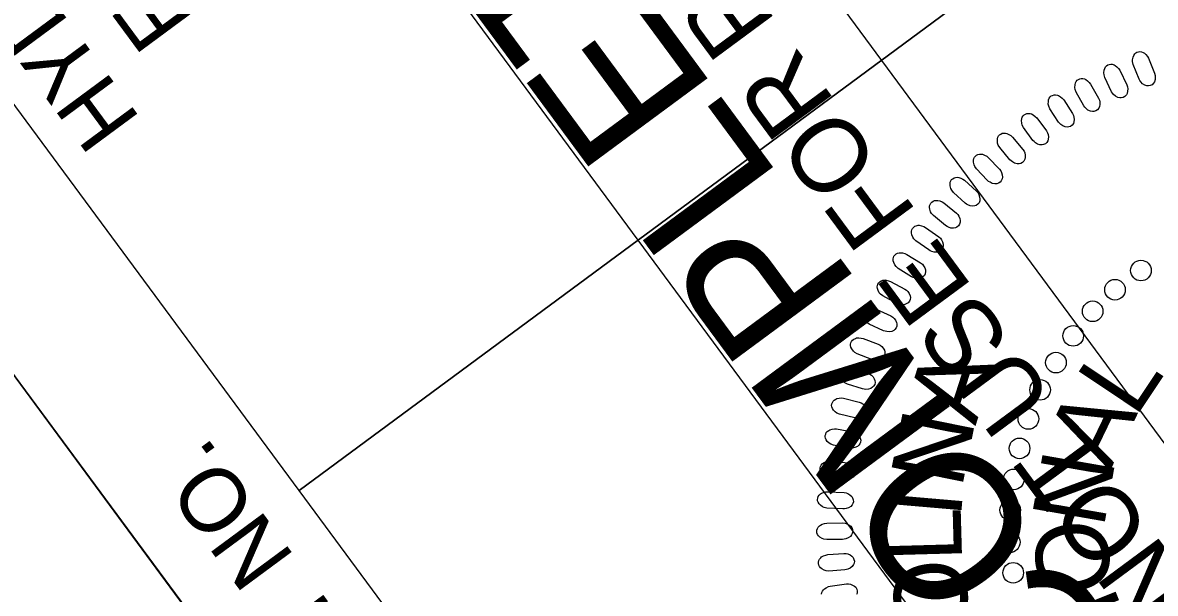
# Model space of a CAD drawing. Extents: x 474314 to 476195, y 501901 to 503905.
# Drawn here: x 474410.1 to 474498.1, y 503188.4 to 503232.7 of the extents above; entities that cross this region are included whole.
import ezdxf

# ---------------------------------------------------------------- set-up
doc = ezdxf.new("R2010")
doc.units = 0
for name, color, linetype in [('Sheet PE Seal Cell', 7, 'Continuous'), ('Sheet Plan CELL', 7, 'Continuous'), ('Sheet Sticker Exception Certification CELL', 7, 'Continuous'), ('Sheet Sticker Incomplete CELL', 7, 'Continuous')]:
    doc.layers.add(name, color=color, linetype=linetype)

msp = doc.modelspace()

# ---------------------------------------------------------------- linework, layer by layer
at = {"layer": 'Sheet PE Seal Cell'}
for points in [[(474496.879, 503228.322), (474496.419, 503229.459), (474496.371, 503229.676), (474496.367, 503229.825), (474496.407, 503230.025), (474496.456, 503230.162), (474496.531, 503230.279), (474496.612, 503230.354), (474496.709, 503230.415), (474496.82, 503230.439), (474496.943, 503230.456), (474497.062, 503230.44), (474497.196, 503230.386), (474497.282, 503230.335), (474497.4, 503230.221), (474497.523, 503230.078), (474497.604, 503229.938), (474498.082, 503228.776), (474498.124, 503228.61), (474498.135, 503228.464), (474498.112, 503228.283), (474498.06, 503228.111), (474498.001, 503228.001), (474497.877, 503227.886), (474497.746, 503227.812), (474497.593, 503227.793), (474497.477, 503227.8), (474497.321, 503227.844), (474497.147, 503227.957), (474497.017, 503228.098), (474496.942, 503228.207)], [(474494.743, 503227.343), (474494.213, 503228.449), (474494.152, 503228.662), (474494.138, 503228.811), (474494.166, 503229.013), (474494.206, 503229.154), (474494.273, 503229.274), (474494.35, 503229.355), (474494.443, 503229.422), (474494.552, 503229.452), (474494.673, 503229.477), (474494.793, 503229.468), (474494.931, 503229.423), (474495.019, 503229.377), (474495.144, 503229.272), (474495.276, 503229.136), (474495.365, 503229.002), (474495.915, 503227.872), (474495.969, 503227.709), (474495.988, 503227.564), (474495.976, 503227.381), (474495.936, 503227.207), (474495.883, 503227.093), (474495.767, 503226.971), (474495.641, 503226.888), (474495.489, 503226.86), (474495.373, 503226.859), (474495.215, 503226.894), (474495.034, 503226.996), (474494.895, 503227.129), (474494.813, 503227.233)], [(474492.587, 503226.243), (474491.988, 503227.315), (474491.914, 503227.524), (474491.891, 503227.671), (474491.906, 503227.875), (474491.937, 503228.018), (474491.996, 503228.142), (474492.068, 503228.228), (474492.157, 503228.3), (474492.264, 503228.337), (474492.383, 503228.369), (474492.503, 503228.368), (474492.643, 503228.332), (474492.734, 503228.292), (474492.866, 503228.194), (474493.006, 503228.067), (474493.104, 503227.939), (474493.724, 503226.845), (474493.787, 503226.686), (474493.816, 503226.543), (474493.815, 503226.36), (474493.786, 503226.183), (474493.74, 503226.066), (474493.632, 503225.937), (474493.512, 503225.847), (474493.361, 503225.809), (474493.246, 503225.801), (474493.086, 503225.826), (474492.9, 503225.916), (474492.752, 503226.039), (474492.664, 503226.138)], [(474490.606, 503224.988), (474489.941, 503226.019), (474489.854, 503226.223), (474489.822, 503226.369), (474489.824, 503226.573), (474489.846, 503226.717), (474489.897, 503226.845), (474489.963, 503226.935), (474490.048, 503227.013), (474490.152, 503227.056), (474490.269, 503227.096), (474490.389, 503227.103), (474490.531, 503227.075), (474490.624, 503227.041), (474490.763, 503226.952), (474490.91, 503226.833), (474491.016, 503226.711), (474491.703, 503225.659), (474491.776, 503225.505), (474491.813, 503225.363), (474491.825, 503225.181), (474491.806, 503225.003), (474491.768, 503224.882), (474491.669, 503224.747), (474491.553, 503224.649), (474491.406, 503224.602), (474491.291, 503224.587), (474491.131, 503224.602), (474490.938, 503224.68), (474490.784, 503224.794), (474490.69, 503224.887)], [(474488.623, 503223.564), (474487.895, 503224.552), (474487.795, 503224.75), (474487.754, 503224.894), (474487.743, 503225.097), (474487.756, 503225.243), (474487.799, 503225.373), (474487.86, 503225.467), (474487.939, 503225.55), (474488.04, 503225.601), (474488.154, 503225.648), (474488.274, 503225.662), (474488.417, 503225.644), (474488.513, 503225.615), (474488.656, 503225.534), (474488.811, 503225.426), (474488.923, 503225.311), (474489.676, 503224.304), (474489.758, 503224.155), (474489.805, 503224.015), (474489.827, 503223.833), (474489.82, 503223.655), (474489.79, 503223.533), (474489.699, 503223.391), (474489.59, 503223.287), (474489.446, 503223.23), (474489.333, 503223.208), (474489.171, 503223.212), (474488.974, 503223.278), (474488.813, 503223.383), (474488.712, 503223.469)], [(474486.837, 503222.06), (474486.049, 503223), (474485.937, 503223.192), (474485.886, 503223.332), (474485.863, 503223.534), (474485.867, 503223.68), (474485.902, 503223.814), (474485.956, 503223.911), (474486.029, 503223.999), (474486.128, 503224.056), (474486.238, 503224.11), (474486.357, 503224.131), (474486.501, 503224.122), (474486.598, 503224.099), (474486.746, 503224.029), (474486.908, 503223.929), (474487.027, 503223.822), (474487.841, 503222.864), (474487.933, 503222.72), (474487.988, 503222.584), (474488.022, 503222.404), (474488.026, 503222.225), (474488.003, 503222.102), (474487.922, 503221.955), (474487.82, 503221.843), (474487.68, 503221.778), (474487.567, 503221.749), (474487.406, 503221.743), (474487.206, 503221.796), (474487.038, 503221.89), (474486.932, 503221.97)], [(474485.08, 503220.459), (474484.234, 503221.348), (474484.109, 503221.532), (474484.05, 503221.669), (474484.015, 503221.869), (474484.009, 503222.016), (474484.035, 503222.151), (474484.083, 503222.252), (474484.151, 503222.343), (474484.246, 503222.406), (474484.353, 503222.467), (474484.47, 503222.497), (474484.615, 503222.496), (474484.713, 503222.48), (474484.865, 503222.418), (474485.033, 503222.329), (474485.159, 503222.229), (474486.031, 503221.325), (474486.132, 503221.186), (474486.196, 503221.054), (474486.241, 503220.877), (474486.256, 503220.699), (474486.24, 503220.574), (474486.169, 503220.422), (474486.073, 503220.304), (474485.938, 503220.231), (474485.828, 503220.195), (474485.667, 503220.179), (474485.464, 503220.219), (474485.291, 503220.303), (474485.18, 503220.376)], [(474483.354, 503218.69), (474482.454, 503219.523), (474482.318, 503219.7), (474482.251, 503219.833), (474482.203, 503220.03), (474482.188, 503220.176), (474482.205, 503220.313), (474482.247, 503220.416), (474482.309, 503220.512), (474482.4, 503220.581), (474482.504, 503220.648), (474482.618, 503220.684), (474482.762, 503220.694), (474482.861, 503220.684), (474483.017, 503220.631), (474483.189, 503220.553), (474483.322, 503220.462), (474484.249, 503219.613), (474484.359, 503219.482), (474484.43, 503219.354), (474484.486, 503219.18), (474484.513, 503219.003), (474484.506, 503218.878), (474484.443, 503218.721), (474484.356, 503218.598), (474484.225, 503218.516), (474484.118, 503218.473), (474483.958, 503218.447), (474483.753, 503218.475), (474483.574, 503218.547), (474483.46, 503218.613)], [(474481.843, 503216.941), (474480.893, 503217.716), (474480.747, 503217.883), (474480.671, 503218.012), (474480.61, 503218.206), (474480.586, 503218.351), (474480.596, 503218.488), (474480.631, 503218.594), (474480.686, 503218.694), (474480.772, 503218.768), (474480.872, 503218.842), (474480.983, 503218.885), (474481.127, 503218.903), (474481.227, 503218.9), (474481.385, 503218.857), (474481.562, 503218.79), (474481.7, 503218.707), (474482.679, 503217.919), (474482.796, 503217.794), (474482.876, 503217.671), (474482.943, 503217.501), (474482.981, 503217.326), (474482.981, 503217.2), (474482.928, 503217.041), (474482.849, 503216.912), (474482.724, 503216.822), (474482.619, 503216.772), (474482.462, 503216.736), (474482.255, 503216.751), (474482.073, 503216.812), (474481.953, 503216.871)], [(474480.538, 503215.051), (474479.54, 503215.765), (474479.383, 503215.923), (474479.3, 503216.046), (474479.228, 503216.236), (474479.194, 503216.379), (474479.195, 503216.517), (474479.223, 503216.625), (474479.273, 503216.728), (474479.354, 503216.807), (474479.448, 503216.887), (474479.557, 503216.937), (474479.7, 503216.964), (474479.799, 503216.967), (474479.961, 503216.935), (474480.141, 503216.879), (474480.284, 503216.804), (474481.311, 503216.079), (474481.435, 503215.963), (474481.522, 503215.844), (474481.6, 503215.679), (474481.649, 503215.507), (474481.657, 503215.381), (474481.615, 503215.218), (474481.543, 503215.085), (474481.424, 503214.987), (474481.323, 503214.931), (474481.167, 503214.885), (474480.96, 503214.887), (474480.775, 503214.936), (474480.652, 503214.987)], [(474479.196, 503212.973), (474478.155, 503213.622), (474477.989, 503213.77), (474477.898, 503213.888), (474477.813, 503214.073), (474477.772, 503214.214), (474477.764, 503214.351), (474477.785, 503214.461), (474477.828, 503214.567), (474477.905, 503214.651), (474477.993, 503214.737), (474478.098, 503214.794), (474478.239, 503214.83), (474478.338, 503214.839), (474478.501, 503214.817), (474478.685, 503214.772), (474478.832, 503214.707), (474479.902, 503214.048), (474480.034, 503213.939), (474480.129, 503213.827), (474480.216, 503213.666), (474480.276, 503213.498), (474480.292, 503213.372), (474480.259, 503213.207), (474480.197, 503213.07), (474480.084, 503212.965), (474479.986, 503212.902), (474479.834, 503212.847), (474479.627, 503212.836), (474479.439, 503212.873), (474479.314, 503212.917)], [(474478.039, 503210.901), (474476.96, 503211.484), (474476.785, 503211.621), (474476.686, 503211.733), (474476.591, 503211.913), (474476.54, 503212.05), (474476.523, 503212.187), (474476.538, 503212.298), (474476.574, 503212.406), (474476.645, 503212.495), (474476.728, 503212.586), (474476.83, 503212.65), (474476.968, 503212.695), (474477.066, 503212.709), (474477.23, 503212.698), (474477.416, 503212.664), (474477.567, 503212.608), (474478.677, 503212.018), (474478.815, 503211.917), (474478.917, 503211.812), (474479.014, 503211.657), (474479.084, 503211.492), (474479.108, 503211.369), (474479.086, 503211.202), (474479.032, 503211.061), (474478.926, 503210.949), (474478.832, 503210.88), (474478.684, 503210.815), (474478.478, 503210.791), (474478.288, 503210.817), (474478.16, 503210.853)], [(474477.021, 503208.773), (474475.907, 503209.287), (474475.724, 503209.413), (474475.619, 503209.518), (474475.512, 503209.691), (474475.453, 503209.825), (474475.428, 503209.961), (474475.436, 503210.073), (474475.464, 503210.183), (474475.53, 503210.276), (474475.607, 503210.372), (474475.704, 503210.442), (474475.839, 503210.496), (474475.936, 503210.516), (474476.101, 503210.515), (474476.289, 503210.494), (474476.443, 503210.447), (474477.587, 503209.928), (474477.732, 503209.836), (474477.84, 503209.737), (474477.947, 503209.588), (474478.026, 503209.429), (474478.059, 503209.307), (474478.047, 503209.139), (474478.003, 503208.995), (474477.904, 503208.876), (474477.815, 503208.802), (474477.671, 503208.728), (474477.467, 503208.691), (474477.275, 503208.705), (474477.145, 503208.732)], [(474476.122, 503206.541), (474474.978, 503206.984), (474474.786, 503207.098), (474474.675, 503207.197), (474474.557, 503207.362), (474474.49, 503207.493), (474474.456, 503207.626), (474474.457, 503207.739), (474474.479, 503207.85), (474474.538, 503207.947), (474474.609, 503208.048), (474474.702, 503208.124), (474474.834, 503208.186), (474474.929, 503208.213), (474475.094, 503208.221), (474475.282, 503208.212), (474475.439, 503208.176), (474476.614, 503207.729), (474476.763, 503207.647), (474476.877, 503207.554), (474476.994, 503207.413), (474477.084, 503207.258), (474477.123, 503207.138), (474477.122, 503206.971), (474477.086, 503206.824), (474476.996, 503206.699), (474476.911, 503206.62), (474476.772, 503206.537), (474476.571, 503206.486), (474476.379, 503206.489), (474476.247, 503206.508)], [(474475.388, 503204.258), (474474.219, 503204.629), (474474.021, 503204.73), (474473.903, 503204.822), (474473.775, 503204.98), (474473.701, 503205.106), (474473.658, 503205.237), (474473.652, 503205.349), (474473.666, 503205.462), (474473.72, 503205.563), (474473.784, 503205.667), (474473.872, 503205.749), (474473.999, 503205.819), (474474.094, 503205.852), (474474.257, 503205.871), (474474.446, 503205.874), (474474.604, 503205.847), (474475.805, 503205.475), (474475.959, 503205.402), (474476.08, 503205.317), (474476.204, 503205.184), (474476.303, 503205.034), (474476.35, 503204.918), (474476.36, 503204.75), (474476.334, 503204.601), (474476.251, 503204.471), (474476.172, 503204.387), (474476.038, 503204.295), (474475.84, 503204.232), (474475.649, 503204.222), (474475.516, 503204.233)], [(474474.79, 503202.001), (474473.599, 503202.297), (474473.395, 503202.386), (474473.272, 503202.471), (474473.135, 503202.62), (474473.052, 503202.741), (474473.002, 503202.869), (474472.988, 503202.98), (474472.996, 503203.094), (474473.042, 503203.198), (474473.1, 503203.307), (474473.184, 503203.394), (474473.306, 503203.472), (474473.398, 503203.51), (474473.559, 503203.539), (474473.747, 503203.554), (474473.908, 503203.537), (474475.129, 503203.241), (474475.288, 503203.178), (474475.413, 503203.101), (474475.546, 503202.976), (474475.655, 503202.833), (474475.709, 503202.719), (474475.729, 503202.553), (474475.712, 503202.403), (474475.637, 503202.268), (474475.564, 503202.178), (474475.436, 503202.079), (474475.243, 503202.004), (474475.052, 503201.982), (474474.919, 503201.984)], [(474474.342, 503199.667), (474473.136, 503199.887), (474472.927, 503199.964), (474472.799, 503200.04), (474472.652, 503200.181), (474472.562, 503200.296), (474472.504, 503200.421), (474472.483, 503200.531), (474472.483, 503200.645), (474472.524, 503200.752), (474472.574, 503200.864), (474472.652, 503200.956), (474472.769, 503201.041), (474472.859, 503201.085), (474473.018, 503201.125), (474473.205, 503201.151), (474473.366, 503201.145), (474474.603, 503200.925), (474474.766, 503200.873), (474474.895, 503200.804), (474475.036, 503200.687), (474475.153, 503200.552), (474475.215, 503200.441), (474475.245, 503200.276), (474475.238, 503200.125), (474475.172, 503199.986), (474475.104, 503199.892), (474474.983, 503199.785), (474474.794, 503199.698), (474474.605, 503199.664), (474474.472, 503199.658)], [(474474.017, 503197.257), (474472.798, 503197.402), (474472.585, 503197.465), (474472.452, 503197.533), (474472.297, 503197.665), (474472.199, 503197.774), (474472.134, 503197.895), (474472.106, 503198.003), (474472.1, 503198.117), (474472.133, 503198.226), (474472.177, 503198.341), (474472.248, 503198.438), (474472.36, 503198.53), (474472.446, 503198.581), (474472.603, 503198.629), (474472.788, 503198.668), (474472.949, 503198.671), (474474.198, 503198.53), (474474.363, 503198.488), (474474.497, 503198.427), (474474.644, 503198.319), (474474.77, 503198.192), (474474.838, 503198.085), (474474.879, 503197.922), (474474.881, 503197.772), (474474.823, 503197.628), (474474.762, 503197.53), (474474.648, 503197.416), (474474.465, 503197.317), (474474.279, 503197.271), (474474.147, 503197.257)], [(474473.851, 503194.933), (474472.626, 503195.001), (474472.409, 503195.05), (474472.273, 503195.11), (474472.109, 503195.231), (474472.005, 503195.334), (474471.932, 503195.451), (474471.898, 503195.557), (474471.885, 503195.671), (474471.91, 503195.781), (474471.947, 503195.899), (474472.012, 503196), (474472.118, 503196.099), (474472.201, 503196.155), (474472.354, 503196.213), (474472.536, 503196.263), (474472.697, 503196.277), (474473.952, 503196.215), (474474.12, 503196.183), (474474.257, 503196.13), (474474.411, 503196.032), (474474.545, 503195.912), (474474.619, 503195.811), (474474.67, 503195.651), (474474.681, 503195.5), (474474.634, 503195.353), (474474.578, 503195.252), (474474.471, 503195.131), (474474.296, 503195.021), (474474.112, 503194.963), (474473.981, 503194.941)], [(474473.837, 503192.567), (474472.611, 503192.558), (474472.391, 503192.594), (474472.251, 503192.645), (474472.081, 503192.756), (474471.97, 503192.852), (474471.889, 503192.963), (474471.849, 503193.069), (474471.828, 503193.181), (474471.847, 503193.292), (474471.876, 503193.412), (474471.935, 503193.517), (474472.034, 503193.623), (474472.113, 503193.684), (474472.263, 503193.752), (474472.441, 503193.813), (474472.601, 503193.836), (474473.858, 503193.853), (474474.027, 503193.832), (474474.167, 503193.788), (474474.327, 503193.7), (474474.468, 503193.589), (474474.549, 503193.492), (474474.609, 503193.336), (474474.63, 503193.186), (474474.592, 503193.036), (474474.542, 503192.931), (474474.444, 503192.803), (474474.275, 503192.683), (474474.096, 503192.614), (474473.967, 503192.583)], [(474474.001, 503190.202), (474472.778, 503190.116), (474472.556, 503190.138), (474472.413, 503190.18), (474472.236, 503190.28), (474472.119, 503190.369), (474472.032, 503190.476), (474471.986, 503190.577), (474471.958, 503190.688), (474471.969, 503190.801), (474471.992, 503190.922), (474472.043, 503191.031), (474472.136, 503191.143), (474472.211, 503191.208), (474472.356, 503191.286), (474472.53, 503191.358), (474472.688, 503191.391), (474473.941, 503191.487), (474474.111, 503191.476), (474474.254, 503191.441), (474474.419, 503191.363), (474474.566, 503191.262), (474474.653, 503191.17), (474474.724, 503191.018), (474474.754, 503190.87), (474474.725, 503190.718), (474474.682, 503190.61), (474474.592, 503190.476), (474474.431, 503190.345), (474474.257, 503190.265), (474474.129, 503190.227)]]:
    msp.add_lwpolyline(points, close=True, dxfattribs=at)
msp.add_lwpolyline([(474472.206, 503188.313), (474472.219, 503188.435), (474472.265, 503188.547), (474472.349, 503188.664), (474472.421, 503188.734), (474472.56, 503188.821), (474472.73, 503188.903), (474472.885, 503188.947), (474474.13, 503189.121), (474474.301, 503189.121), (474474.445, 503189.096), (474474.615, 503189.028), (474474.769, 503188.935), (474474.86, 503188.85), (474474.941, 503188.702), (474474.98, 503188.556), (474474.961, 503188.403), (474474.925, 503188.292)], dxfattribs=at)
for centre in [(474497.02, 503213.452), (474495.001, 503211.962), (474493.267, 503210.286), (474491.754, 503208.378), (474490.415, 503206.301), (474489.183, 503204.183), (474488.273, 503201.928), (474487.585, 503199.639), (474487.136, 503197.229), (474486.862, 503194.85), (474486.826, 503192.349), (474487.094, 503189.974)]:
    msp.add_circle(centre, 0.801, dxfattribs=at)
at = {"layer": 'Sheet Plan CELL'}
for p, q in [((474481, 503108.466), (474362.144, 503269.364)), ((474481, 503108.466), (474362.144, 503269.364)), ((474431.609, 503196.366), (474522.068, 503263.187))]:
    msp.add_line(p, q, dxfattribs=at)
for points in [[(474431.609, 503196.366), (474372.199, 503276.79), (474462.698, 503343.64), (474522.115, 503263.206)], [(474460.82, 503093.562), (474341.971, 503254.513), (474362.144, 503269.364), (474481, 503108.466)], [(474491.045, 503115.885), (474431.609, 503196.366), (474522.115, 503263.206), (474581.524, 503182.72)]]:
    msp.add_lwpolyline(points, close=True, dxfattribs=at)
at = {"layer": 'Sheet Sticker Incomplete CELL'}
msp.add_lwpolyline([(474520.521, 503170.658), (474501.617, 503156.697), (474414.289, 503274.946), (474433.193, 503288.907)], close=True, dxfattribs=at)

# ---------------------------------------------------------------- texts
at = {"layer": 'Sheet PE Seal Cell'}
for s, rotation, p in [('A', 72.11917, (474484.155, 503201.355)), ('L', 56.2772, (474496.562, 503201.95)), ('A', 64.217, (474494.61, 503197.869)), ('N', 78.60853, (474483.086, 503196.439)), ('N', 80.09659, (474494.114, 503193.354)), ('I', 85.09788, (474483.016, 503194.144)), ('L', 91.58724, (474483.126, 503190.876)), ('O', 95.97619, (474494.822, 503188.517)), ('O', 98.0766, (474483.901, 503185.565)), ('I', 111.85578, (474495.577, 503187.206))]:
    msp.add_text(s, height=5.669, rotation=rotation, dxfattribs=at).set_placement(p)
at = {"layer": 'Sheet Plan CELL'}
for s, p in [('ENGINEER', (474423.534, 503232.949)), ('HYDRAULICS', (474419.364, 503225.192)), ('R/W SHEET NO.', (474454.529, 503159.776))]:
    msp.add_text(s, height=5.0001, rotation=126.44635, dxfattribs=at).set_placement(p)
at = {"layer": 'Sheet Sticker Exception Certification CELL'}
msp.add_text('DOCUMENT NOT CONSIDERED FINAL', height=5.5, rotation=126.44635, dxfattribs=at).set_placement((474577.329, 503205.816))
msp.add_text('DOCUMENT NOT CONSIDERED FINAL', height=5.5, rotation=126.44635, dxfattribs=at).set_placement((474577.329, 503205.816))
at = {"layer": 'Sheet Sticker Incomplete CELL'}
for s, height, p in [('INCOMPLETE PLANS', 11.52, (474505.793, 503170.907)), ('DO NOT USE FOR R/W ACQUISITION', 5.76, (474509.452, 503177.65))]:
    msp.add_text(s, height=height, rotation=126.44635, dxfattribs=at).set_placement(p)

doc.saveas('drawing.dxf')
